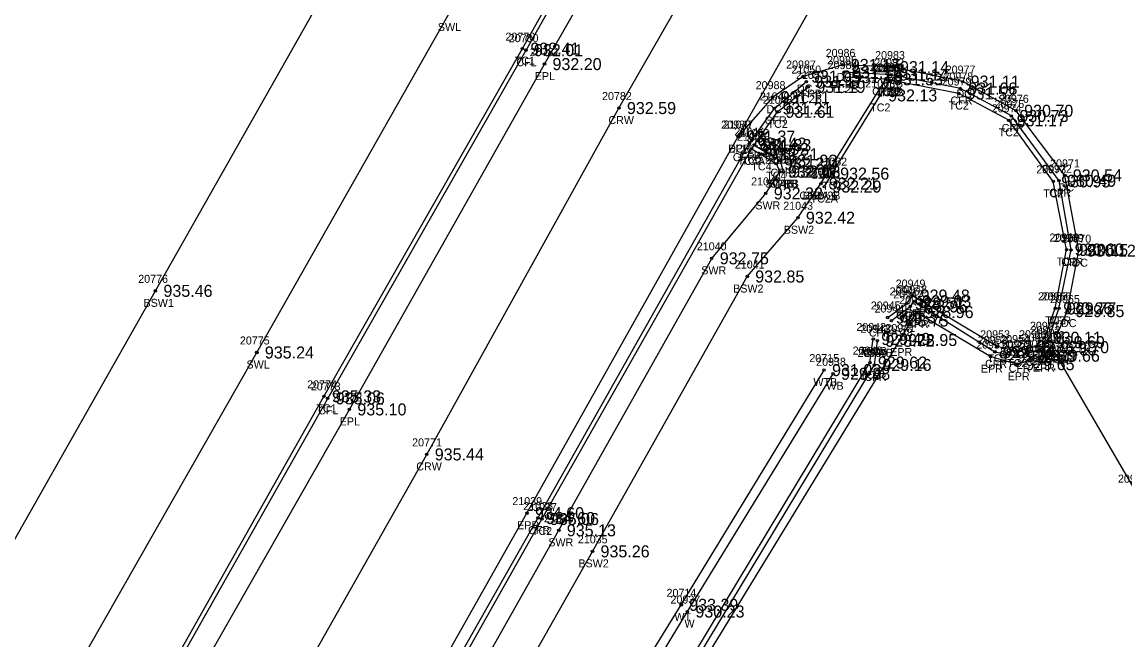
# Model space of a CAD drawing. Extents: x 1576181 to 1577685, y 1099396 to 1101490.
# Drawn here: x 1576648.9 to 1576786.7, y 1100049.3 to 1100126.4 of the extents above; entities that cross this region are included whole.
import ezdxf

# ---------------------------------------------------------------- set-up
doc = ezdxf.new("R2010")
doc.units = 0
for name, color, linetype in [('RD_DTM_BkLn1', 7, 'Continuous'), ('RD_DTM_BkLn2', 7, 'Continuous'), ('RD_EX_BldgApp', 7, 'Continuous'), ('RD_EX_Conc', 7, 'Continuous'), ('RD_EX_Conc_txCode', 7, 'Continuous'), ('RD_EX_Misc_txCode', 7, 'Continuous'), ('RD_EX_Road', 7, 'Continuous'), ('RD_EX_Road_txCode', 7, 'Continuous'), ('RD_EX_TX_Conc_ELEV', 7, 'Continuous'), ('RD_EX_TX_Misc_ELEV', 7, 'Continuous'), ('RD_EX_TX_Road_ELEV', 7, 'Continuous'), ('RD_HC_Survey_ELEV', 7, 'Continuous'), ('RD_HC_Survey_txCode', 7, 'Continuous'), ('RD_SMD_Locator', 7, 'Continuous')]:
    doc.layers.add(name, color=color, linetype=linetype)

msp = doc.modelspace()

# ---------------------------------------------------------------- linework, layer by layer
at = {"layer": 'RD_DTM_BkLn1'}
msp.add_lwpolyline([(1576435.96, 1099635.47), (1576469.98, 1099685.91), (1576496.51, 1099728.46), (1576522.67, 1099770.85), (1576549.06, 1099813.4), (1576563.36, 1099837.2), (1576575.09, 1099855.95), (1576600.75, 1099898.96), (1576625.57, 1099942.14), (1576652.37, 1099988.91), (1576675.03, 1100029.12), (1576699.51, 1100072.44), (1576723.52, 1100115.7), (1576748.08, 1100158.53), (1576774.13, 1100203.85), (1576797.97, 1100246.52), (1576822.46, 1100289.82), (1576846.93, 1100333.35), (1576871.37, 1100376.46), (1576888.27, 1100406.22)], dxfattribs=at)
at = {"layer": 'RD_DTM_BkLn2'}
for points in [[(1576569.71, 1099889.13), (1576574.56, 1099891.34), (1576579.27, 1099894.47), (1576584.19, 1099899.55), (1576592.25, 1099913.59), (1576612.84, 1099949.87), (1576637.54, 1099993.05), (1576637.54, 1099993.05), (1576662.19, 1100036.34), (1576686.67, 1100079.69), (1576711.46, 1100123.12), (1576735.92, 1100166.59), (1576760.76, 1100210.19), (1576785.21, 1100253.55), (1576809.13, 1100296.43), (1576833.85, 1100340.61), (1576852.06, 1100373.52), (1576858.66, 1100385.37)], [(1576749.19, 1100105.9), (1576750.16, 1100107.51), (1576756.16, 1100117.28), (1576757.41, 1100119.17)], [(1576757.11, 1100089.54), (1576759.48, 1100091.3), (1576760.22, 1100092.28), (1576770.78, 1100085.94), (1576773.28, 1100085.35), (1576775.63, 1100085.95), (1576776.72, 1100087.01), (1576778.03, 1100090.69), (1576779.46, 1100098.03), (1576777.79, 1100106.54), (1576772.22, 1100114.17), (1576765.97, 1100117.52), (1576757.41, 1100119.17), (1576756.86, 1100119.29), (1576751.73, 1100119.57)], [(1576665.05, 1099978.47), (1576689.17, 1100020.51), (1576713.89, 1100064.37), (1576740.09, 1100110.61), (1576743.33, 1100115.23), (1576747.19, 1100118.34)], [(1576740.09, 1100110.61), (1576741.31, 1100109.92), (1576743.17, 1100108.76), (1576743.62, 1100107.75)], [(1576691.33, 1099981.62), (1576693.77, 1099982.83), (1576694.95, 1099984.59), (1576706.06, 1099977.71), (1576709.96, 1099976.95), (1576712.68, 1099979.05), (1576716.84, 1099986.32), (1576717.28, 1099989.03), (1576715.05, 1099991.93), (1576703.59, 1099998.96), (1576727.24, 1100038.12), (1576754.88, 1100083.91), (1576755.29, 1100086.86)], [(1576682.86, 1099868.56), (1576662.28, 1099880.96), (1576644.68, 1099891.53), (1576640.03, 1099896.91), (1576640.01, 1099902.65), (1576645.38, 1099914.36), (1576654.84, 1099929.02), (1576680.05, 1099970.19), (1576705.64, 1100012.05), (1576731.3, 1100053.65), (1576749.15, 1100082.97)]]:
    msp.add_lwpolyline(points, dxfattribs=at)
at = {"layer": 'RD_EX_BldgApp'}
msp.add_lwpolyline([(1576672.29, 1099877.61), (1576646.3, 1099893.42), (1576642.27, 1099901.79), (1576647.56, 1099912.99), (1576656.83, 1099928.62), (1576681.63, 1099969.33), (1576707.3, 1100011.85), (1576732.08, 1100052.81), (1576750.28, 1100082.51)], dxfattribs=at)
at = {"layer": 'RD_EX_Conc'}
msp.add_line((1576748.75, 1100106.27), (1576756.86, 1100119.29), dxfattribs=at)
for points in [[(1576537.53, 1099904.47), (1576543.86, 1099909.52), (1576562.16, 1099910.99), (1576591.51, 1099962.44), (1576615.66, 1100005.02), (1576615.66, 1100005.02), (1576639.95, 1100047.65), (1576665.61, 1100092.87), (1576689.57, 1100135.17), (1576714.68, 1100179.66), (1576738.99, 1100222.53), (1576763.6, 1100265.87), (1576774.84, 1100284.48), (1576788.69, 1100308.17), (1576806.14, 1100353.34), (1576815.02, 1100384.28), (1576820.35, 1100399.92), (1576825.22, 1100406.93), (1576832.15, 1100418.17), (1576835.04, 1100423.11), (1576847.13, 1100416.35), (1576868.44, 1100408.23), (1576872.09, 1100412.69)], [(1576592.25, 1099913.59), (1576580.2, 1099912.49), (1576604.17, 1099954.86), (1576628.85, 1099997.89), (1576628.85, 1099997.89), (1576652.81, 1100040.47), (1576678.28, 1100085.17), (1576702.19, 1100127.32), (1576727.43, 1100172.04), (1576752.1, 1100215.39), (1576776.49, 1100258.76), (1576788, 1100277.34), (1576801.96, 1100301.42), (1576820.18, 1100348.3), (1576829.19, 1100379.59), (1576833.87, 1100393.41), (1576838.32, 1100402.43), (1576861.82, 1100391.11)], [(1576569.87, 1099888.69), (1576574.84, 1099890.86), (1576574.84, 1099890.86), (1576579.65, 1099894.15), (1576584.72, 1099899.29), (1576592.68, 1099913.3), (1576613.45, 1099949.72), (1576638.02, 1099992.78), (1576638.02, 1099992.78), (1576662.6, 1100036.05), (1576687.14, 1100079.44), (1576711.91, 1100122.93), (1576736.42, 1100166.35), (1576761.24, 1100209.96), (1576785.67, 1100253.17), (1576809.57, 1100296.25), (1576834.31, 1100340.56), (1576852.46, 1100373.22), (1576852.46, 1100373.22), (1576859.24, 1100385.1)], [(1576788.06, 1100067.91), (1576777.62, 1100085.83), (1576779.54, 1100090.34), (1576780.97, 1100097.89), (1576779.23, 1100107.29), (1576773.15, 1100115.36), (1576766.47, 1100119.01), (1576757.64, 1100120.82), (1576751.5, 1100121.09), (1576746.53, 1100119.64), (1576742.73, 1100117.06), (1576738.42, 1100112.14)], [(1576757.57, 1100089.16), (1576759.92, 1100090.92), (1576760.41, 1100091.57), (1576770.49, 1100085.25), (1576773.43, 1100084.71), (1576776.08, 1100085.54), (1576777.11, 1100086.46), (1576778.5, 1100090.67), (1576780.01, 1100097.98), (1576778.51, 1100106.62), (1576772.56, 1100114.71), (1576766.18, 1100118.14), (1576757.54, 1100119.87), (1576751.65, 1100120.18)], [(1576664.48, 1099978.73), (1576688.59, 1100020.79), (1576713.4, 1100064.49), (1576739.81, 1100111.26), (1576742.95, 1100115.66), (1576746.94, 1100119.01)], [(1576740.42, 1100111.07), (1576743.68, 1100109.13), (1576744.06, 1100107.76)], [(1576604.88, 1099870.26), (1576606.18, 1099869.97), (1576617.18, 1099889.59), (1576642.12, 1099933.62), (1576667.46, 1099977.42), (1576667.46, 1099977.42), (1576691.07, 1100018.79), (1576716.01, 1100062.96), (1576735.12, 1100096.93), (1576741.87, 1100105.04), (1576743.62, 1100107.75)], [(1576611.55, 1099868.43), (1576613.25, 1099872.41), (1576617.21, 1099879.29), (1576621.44, 1099887.05), (1576646.34, 1099930.82), (1576671.48, 1099974.6), (1576671.48, 1099974.6), (1576695.54, 1100016.68), (1576720.22, 1100060.33), (1576739.55, 1100094.66), (1576745.88, 1100102), (1576748.75, 1100106.27)], [(1576691.74, 1099981.25), (1576694.2, 1099982.62), (1576695.12, 1099983.85), (1576705.73, 1099977.15), (1576710.01, 1099976.47), (1576713.24, 1099978.71), (1576717.29, 1099985.96), (1576717.77, 1099989.3), (1576715.19, 1099992.27), (1576704.3, 1099999.11), (1576727.81, 1100037.82), (1576755.44, 1100083.61), (1576755.82, 1100086.63)]]:
    msp.add_lwpolyline(points, dxfattribs=at)
at = {"layer": 'RD_EX_Road'}
for points in [[(1576574.84, 1099890.86), (1576581.17, 1099887.16), (1576595.39, 1099911.97), (1576615.87, 1099948.17), (1576640.56, 1099991.4), (1576640.56, 1099991.4), (1576664.88, 1100034.19), (1576689.84, 1100078.06), (1576714.22, 1100121.19), (1576739.08, 1100164.66), (1576764.15, 1100209.11), (1576788.31, 1100251.8), (1576812.15, 1100294.46), (1576837.06, 1100339.37), (1576855.38, 1100371.53), (1576853.98, 1100372.48), (1576862.98, 1100388.86), (1576865.16, 1100391.95), (1576873.15, 1100402.8), (1576877.45, 1100410.32)], [(1576663.31, 1099979.53), (1576687.43, 1100021.53), (1576712.03, 1100065.1), (1576738.42, 1100112.14), (1576760.61, 1100151.41), (1576785.78, 1100195.96), (1576800.59, 1100221.87), (1576817.54, 1100252.08), (1576858.25, 1100324.63), (1576880.45, 1100364.01), (1576883.5, 1100369.45), (1576896.98, 1100397.71)], [(1576683.42, 1099888.98), (1576666.06, 1099899.54), (1576667.21, 1099902.21), (1576666.94, 1099905.87), (1576664.42, 1099908.53), (1576653.81, 1099914.11), (1576693.12, 1099978.42), (1576695.37, 1099982.47), (1576705.19, 1099976.43), (1576710.33, 1099975.62), (1576713.96, 1099978.17), (1576718.08, 1099985.44), (1576718.51, 1099989.55), (1576715.55, 1099993.27), (1576705.56, 1099999.56), (1576728.51, 1100037.37), (1576758.65, 1100086.73), (1576760.7, 1100090.22), (1576769.98, 1100084.65), (1576773.31, 1100083.71), (1576776.47, 1100084.77), (1576777.62, 1100085.83)]]:
    msp.add_lwpolyline(points, dxfattribs=at)
at = {"layer": 'RD_SMD_Locator'}
for centre in [(1576711.46, 1100123.12), (1576711.91, 1100122.93), (1576714.22, 1100121.19), (1576751.5, 1100121.09), (1576751.65, 1100120.18), (1576757.54, 1100119.87), (1576757.64, 1100120.82), (1576746.53, 1100119.64), (1576746.94, 1100119.01), (1576747.19, 1100118.34), (1576751.73, 1100119.57), (1576756.86, 1100119.29), (1576756.86, 1100119.29), (1576757.41, 1100119.17), (1576757.41, 1100119.17), (1576766.47, 1100119.01), (1576742.73, 1100117.06), (1576756.16, 1100117.28), (1576765.97, 1100117.52), (1576766.18, 1100118.14), (1576723.52, 1100115.7), (1576742.95, 1100115.66), (1576743.33, 1100115.23), (1576772.56, 1100114.71), (1576773.15, 1100115.36), (1576772.22, 1100114.17), (1576738.42, 1100112.14), (1576738.42, 1100112.14), (1576739.81, 1100111.26), (1576740.09, 1100110.61), (1576740.09, 1100110.61), (1576740.42, 1100111.07), (1576741.31, 1100109.92), (1576743.17, 1100108.76), (1576743.68, 1100109.13), (1576743.62, 1100107.75), (1576743.62, 1100107.75), (1576744.06, 1100107.76), (1576750.16, 1100107.51), (1576748.75, 1100106.27), (1576748.75, 1100106.27), (1576777.79, 1100106.54), (1576778.51, 1100106.62), (1576779.23, 1100107.29), (1576741.87, 1100105.04), (1576749.19, 1100105.9), (1576745.88, 1100102), (1576779.46, 1100098.03), (1576780.01, 1100097.98), (1576780.97, 1100097.89), (1576735.12, 1100096.93), (1576739.55, 1100094.66), (1576665.61, 1100092.87), (1576760.22, 1100092.28), (1576759.48, 1100091.3), (1576759.92, 1100090.92), (1576760.41, 1100091.57), (1576757.11, 1100089.54), (1576760.7, 1100090.22), (1576778.03, 1100090.69), (1576778.5, 1100090.67), (1576779.54, 1100090.34), (1576757.57, 1100089.16), (1576755.29, 1100086.86), (1576758.65, 1100086.73), (1576776.72, 1100087.01), (1576755.82, 1100086.63), (1576770.78, 1100085.94), (1576773.28, 1100085.35), (1576775.63, 1100085.95), (1576776.08, 1100085.54), (1576777.11, 1100086.46), (1576777.62, 1100085.83), (1576777.62, 1100085.83), (1576678.28, 1100085.17), (1576754.88, 1100083.91), (1576769.98, 1100084.65), (1576770.49, 1100085.25), (1576773.43, 1100084.71), (1576776.47, 1100084.77), (1576749.15, 1100082.97), (1576750.28, 1100082.51), (1576755.44, 1100083.61), (1576773.31, 1100083.71), (1576686.67, 1100079.69), (1576687.14, 1100079.44), (1576689.84, 1100078.06), (1576699.51, 1100072.44), (1576712.03, 1100065.1), (1576713.4, 1100064.49), (1576713.89, 1100064.37), (1576716.01, 1100062.96), (1576720.22, 1100060.33), (1576731.3, 1100053.65), (1576732.08, 1100052.81)]:
    msp.add_circle(centre, 0.15, dxfattribs=at)

# ---------------------------------------------------------------- texts
at = {"layer": 'RD_EX_Conc_txCode'}
for s, p in [('SWL', (1576700.9, 1100125.32)), ('20779', (1576709.34, 1100124.12)), ('20780', (1576709.75, 1100123.93)), ('20986', (1576749.35, 1100122.09)), ('20983', (1576755.53, 1100121.82)), ('TC1', (1576710.5, 1100121.12)), ('CFL', (1576710.7, 1100120.93)), ('20987', (1576744.41, 1100120.64)), ('20985', (1576749.53, 1100121.18)), ('20984', (1576749.61, 1100120.57)), ('21065', (1576755, 1100120.29)), ('20981', (1576755.03, 1100120.29)), ('20982', (1576755.42, 1100120.87)), ('21050', (1576745.07, 1100120.01)), ('21051', (1576745.64, 1100119.34)), ('DC', (1576750.72, 1100119.09)), ('20980', (1576755.25, 1100120.17)), ('21064', (1576755.55, 1100120.17)), ('20978', (1576764.06, 1100119.14)), ('20977', (1576764.35, 1100120.01)), ('20988', (1576740.61, 1100118.06)), ('DC', (1576745.75, 1100117.64)), ('CFRB', (1576749.95, 1100118.18)), ('TC2B', (1576750.01, 1100117.57)), ('21063', (1576754.3, 1100118.28)), ('CFR', (1576756.31, 1100117.87)), ('DC', (1576756.86, 1100118.82)), ('20979', (1576763.85, 1100118.52)), ('21049', (1576741.12, 1100116.66)), ('21048', (1576741.5, 1100116.23)), ('CFRB', (1576745.24, 1100117.01)), ('TC2B', (1576745.48, 1100116.34)), ('CFRB', (1576755.16, 1100117.29)), ('TC2', (1576755.62, 1100117.29)), ('TC2B', (1576755.69, 1100117.17)), ('TC2', (1576756.16, 1100117.17)), ('CFR', (1576764.95, 1100116.14)), ('DC', (1576765.69, 1100117.01)), ('20976', (1576771.01, 1100116.36)), ('DC', (1576741.95, 1100115.06)), ('TC2', (1576754.91, 1100115.28)), ('TC2', (1576764.72, 1100115.52)), ('20974', (1576770.1, 1100115.17)), ('20975', (1576770.45, 1100115.71)), ('CFR', (1576741.73, 1100113.66)), ('DC', (1576772.37, 1100113.36)), ('20989', (1576736.3, 1100113.14)), ('21046', (1576737.95, 1100112.26)), ('21052', (1576738.59, 1100112.07)), ('TC2', (1576742.09, 1100113.23)), ('TC2', (1576770.97, 1100112.17)), ('CFR', (1576771.34, 1100112.71)), ('21044', (1576738.26, 1100111.61)), ('21045', (1576738.26, 1100111.61)), ('21053', (1576739.47, 1100110.92)), ('DCB', (1576737.16, 1100110.14)), ('CFR', (1576738.58, 1100109.26)), ('21054', (1576741.33, 1100109.76)), ('21055', (1576741.85, 1100110.13)), ('CFRA 6', (1576737.75, 1100109.07)), ('TC4A', (1576738.36, 1100108.61)), ('TC2', (1576738.85, 1100108.61)), ('TC4', (1576740.07, 1100107.92)), ('21057', (1576741.79, 1100108.75)), ('21058', (1576741.79, 1100108.75)), ('21056', (1576742.2, 1100108.76)), ('21062', (1576748.31, 1100108.51)), ('20971', (1576777.39, 1100108.29)), ('TC4', (1576741.92, 1100106.76)), ('CFR', (1576742.45, 1100107.13)), ('21060', (1576746.85, 1100107.27)), ('21059', (1576746.91, 1100107.27)), ('21061', (1576747.61, 1100106.9)), ('20973', (1576775.67, 1100107.54)), ('20972', (1576776.39, 1100107.62)), ('21042', (1576740.04, 1100106.04)), ('SWRB', (1576741.83, 1100105.75)), ('TC4B', (1576741.9, 1100105.75)), ('CFRB', (1576742.36, 1100105.76)), ('TC2', (1576748.92, 1100105.51)), ('DC', (1576778.45, 1100105.29)), ('CFRA 6', (1576746.07, 1100104.27)), ('BSW2B', (1576746.51, 1100104.27)), ('TC2A', (1576747.46, 1100103.9)), ('TC2', (1576776.55, 1100104.54)), ('CFR', (1576777.28, 1100104.62)), ('SWR', (1576740.56, 1100103.04)), ('21043', (1576744.05, 1100103)), ('BSW2', (1576744.12, 1100100)), ('20968', (1576777.32, 1100099.03)), ('20969', (1576777.87, 1100098.98)), ('20970', (1576778.81, 1100098.89)), ('21040', (1576733.25, 1100097.93)), ('21041', (1576738, 1100095.66)), ('TC2', (1576778.22, 1100096.03)), ('CFR', (1576778.79, 1100095.98)), ('DC', (1576780.19, 1100095.89)), ('SWR', (1576733.81, 1100094.93)), ('20776', (1576663.46, 1100093.87)), ('20949', (1576758.1, 1100093.28)), ('BSW2', (1576737.79, 1100092.66)), ('20946', (1576757.34, 1100092.3)), ('20947', (1576757.8, 1100091.92)), ('20948', (1576758.3, 1100092.57)), ('20967', (1576775.89, 1100091.69)), ('20966', (1576776.33, 1100091.67)), ('20965', (1576777.4, 1100091.34)), ('BSW1', (1576664.12, 1100090.87)), ('20945', (1576754.99, 1100090.54)), ('20944', (1576755.46, 1100090.16)), ('TC2', (1576758.97, 1100090.28)), ('TC2', (1576758.24, 1100089.3)), ('CFR', (1576758.69, 1100088.92)), ('CFR', (1576759.19, 1100089.57)), ('TC2', (1576776.78, 1100088.69)), ('CFR', (1576777.27, 1100088.67)), ('20942', (1576753.18, 1100087.86)), ('20943', (1576753.7, 1100087.63)), ('CFRA 18', (1576754.75, 1100087.16)), ('TC2A', (1576755.37, 1100087.54)), ('20961', (1576774.87, 1100088.01)), ('20962', (1576774.96, 1100087.46)), ('DC', (1576778.76, 1100088.34)), ('20775', (1576676.16, 1100086.17)), ('20952', (1576768.37, 1100086.25)), ('20953', (1576768.66, 1100086.94)), ('20954', (1576771.16, 1100086.35)), ('20959', (1576773.51, 1100086.95)), ('20958', (1576773.96, 1100086.54)), ('20963', (1576775.48, 1100086.83)), ('20940', (1576752.72, 1100084.91)), ('20939', (1576753.32, 1100084.61)), ('TC2B', (1576753.58, 1100084.86)), ('CFRB', (1576754.12, 1100084.63)), ('20955', (1576771.32, 1100085.71)), ('TC2', (1576775.48, 1100085.01)), ('CFR', (1576775.88, 1100084.46)), ('SWL', (1576676.99, 1100083.17)), ('CFR', (1576769.26, 1100083.25)), ('TC2', (1576769.54, 1100083.94)), ('TC2', (1576772.04, 1100083.35)), ('TC2', (1576774.39, 1100083.95)), ('CFR', (1576774.85, 1100083.54)), ('DC', (1576776.84, 1100083.83)), ('TC2', (1576753.64, 1100081.91)), ('CFR', (1576772.21, 1100082.71)), ('20774', (1576684.56, 1100080.69)), ('20773', (1576685.02, 1100080.44)), ('CFR', (1576754.21, 1100081.61)), ('TC1', (1576685.71, 1100077.69)), ('CFL', (1576685.94, 1100077.44)), ('20960', (1576785.87, 1100068.91)), ('21038', (1576711.57, 1100065.49)), ('21037', (1576712.06, 1100065.37)), ('21036', (1576714.15, 1100063.96)), ('CFR', (1576712.17, 1100062.49)), ('TC2', (1576712.65, 1100062.37)), ('21035', (1576718.39, 1100061.33)), ('SWR', (1576714.7, 1100060.96)), ('BSW2', (1576718.46, 1100058.33))]:
    msp.add_text(s, height=1, dxfattribs=at).set_placement(p)
at = {"layer": 'RD_EX_Misc_txCode'}
for s, p in [('20715', (1576747.31, 1100083.97)), ('20938', (1576748.16, 1100083.51)), ('WTB', (1576747.82, 1100080.97)), ('WB', (1576749.44, 1100080.51)), ('20714', (1576729.47, 1100054.65)), ('20937', (1576729.96, 1100053.81)), ('WT', (1576730.45, 1100051.65)), ('W', (1576731.71, 1100050.81))]:
    msp.add_text(s, height=1, dxfattribs=at).set_placement(p)
at = {"layer": 'RD_EX_Road_txCode'}
for s, p in [('20781', (1576712.38, 1100122.19)), ('EPL', (1576713.01, 1100119.19)), ('21047', (1576736.58, 1100113.14)), ('EPR', (1576737.19, 1100110.14)), ('20950', (1576758.54, 1100091.22)), ('20941', (1576756.81, 1100087.73)), ('EPR', (1576759.47, 1100088.22)), ('20964', (1576775.48, 1100086.83)), ('EPR', (1576757.42, 1100084.73)), ('20951', (1576768.15, 1100085.65)), ('20956', (1576771.17, 1100084.71)), ('20957', (1576774.35, 1100085.77)), ('EPRB', (1576775.92, 1100083.83)), ('EPR', (1576768.75, 1100082.65)), ('EPR', (1576772.09, 1100081.71)), ('EPR', (1576775.24, 1100082.77)), ('20772', (1576687.72, 1100079.06)), ('EPL', (1576688.64, 1100076.06)), ('21039', (1576710.2, 1100066.1)), ('EPR', (1576710.8, 1100063.1))]:
    msp.add_text(s, height=1, dxfattribs=at).set_placement(p)
at = {"layer": 'RD_EX_TX_Conc_ELEV'}
for s, p in [('932.41', (1576712.46, 1100122.37)), ('932.01', (1576712.91, 1100122.18)), ('931.17', (1576752.5, 1100120.34)), ('931.14', (1576758.64, 1100120.07)), ('931.05', (1576747.53, 1100118.89)), ('931.12', (1576752.65, 1100119.43)), ('931.18', (1576752.73, 1100118.82)), ('931.53', (1576757.86, 1100118.54)), ('931.53', (1576757.86, 1100118.54)), ('931.63', (1576758.41, 1100118.42)), ('931.55', (1576758.41, 1100118.42)), ('931.14', (1576758.54, 1100119.12)), ('931.17', (1576747.94, 1100118.26)), ('931.19', (1576748.19, 1100117.59)), ('931.08', (1576767.18, 1100117.39)), ('931.11', (1576767.47, 1100118.26)), ('931.11', (1576743.73, 1100116.31)), ('932.13', (1576757.16, 1100116.53)), ('931.52', (1576766.97, 1100116.77)), ('931.21', (1576743.95, 1100114.91)), ('931.61', (1576744.33, 1100114.48)), ('930.70', (1576774.15, 1100114.61)), ('931.17', (1576773.22, 1100113.42)), ('930.73', (1576773.56, 1100113.96)), ('931.37', (1576739.42, 1100111.39)), ('931.42', (1576740.81, 1100110.51)), ('931.83', (1576741.42, 1100110.32)), ('931.92', (1576741.09, 1100109.86)), ('931.92', (1576741.09, 1100109.86)), ('932.21', (1576742.31, 1100109.17)), ('932.21', (1576744.17, 1100108.01)), ('931.93', (1576744.68, 1100108.38)), ('932.12', (1576744.62, 1100107)), ('932.12', (1576744.62, 1100107)), ('932.13', (1576745.06, 1100107.01)), ('932.56', (1576751.16, 1100106.76)), ('930.54', (1576780.23, 1100106.54)), ('932.21', (1576749.75, 1100105.52)), ('932.21', (1576749.75, 1100105.52)), ('932.29', (1576750.19, 1100105.15)), ('930.95', (1576778.79, 1100105.79)), ('930.49', (1576779.51, 1100105.87)), ('932.32', (1576742.87, 1100104.29)), ('932.42', (1576746.88, 1100101.25)), ('930.60', (1576780.46, 1100097.28)), ('930.15', (1576781.01, 1100097.23)), ('930.12', (1576781.97, 1100097.14)), ('932.75', (1576736.12, 1100096.18)), ('932.85', (1576740.55, 1100093.91)), ('935.46', (1576666.61, 1100092.12)), ('929.48', (1576761.22, 1100091.53)), ('929.03', (1576761.41, 1100090.82)), ('929.51', (1576760.48, 1100090.55)), ('928.96', (1576760.92, 1100090.17)), ('930.26', (1576779.03, 1100089.94)), ('929.77', (1576779.5, 1100089.92)), ('929.85', (1576780.54, 1100089.59)), ('929.37', (1576758.11, 1100088.79)), ('928.75', (1576758.57, 1100088.41)), ('929.49', (1576756.29, 1100086.11)), ('928.72', (1576756.82, 1100085.88)), ('930.11', (1576777.72, 1100086.26)), ('929.69', (1576778.11, 1100085.71)), ('935.24', (1576679.28, 1100084.42)), ('929.59', (1576771.49, 1100084.5)), ('930.02', (1576771.78, 1100085.19)), ('930.04', (1576774.28, 1100084.6)), ('929.60', (1576774.43, 1100083.96)), ('930.12', (1576776.63, 1100085.2)), ('929.60', (1576777.08, 1100084.79)), ('929.70', (1576778.62, 1100085.08)), ('929.62', (1576755.88, 1100083.16)), ('929.16', (1576756.44, 1100082.86)), ('935.33', (1576687.67, 1100078.94)), ('935.06', (1576688.14, 1100078.69)), ('934.60', (1576714.4, 1100063.74)), ('935.06', (1576714.89, 1100063.62)), ('935.13', (1576717.01, 1100062.21)), ('935.26', (1576721.22, 1100059.58))]:
    msp.add_text(s, height=1.5, dxfattribs=at).set_placement(p)
at = {"layer": 'RD_EX_TX_Misc_ELEV'}
for s, p in [('931.03', (1576750.15, 1100082.22)), ('929.88', (1576751.28, 1100081.76)), ('933.39', (1576732.3, 1100052.9)), ('930.23', (1576733.08, 1100052.06))]:
    msp.add_text(s, height=1.5, dxfattribs=at).set_placement(p)
at = {"layer": 'RD_EX_TX_Road_ELEV'}
for s, p in [('932.20', (1576715.22, 1100120.44)), ('931.37', (1576739.42, 1100111.39)), ('928.96', (1576761.7, 1100089.47)), ('928.95', (1576759.65, 1100085.98)), ('929.57', (1576770.98, 1100083.9)), ('929.66', (1576777.47, 1100084.02)), ('929.70', (1576778.62, 1100085.08)), ('929.65', (1576774.31, 1100082.96)), ('935.10', (1576690.84, 1100077.31)), ('934.60', (1576713.03, 1100064.35))]:
    msp.add_text(s, height=1.5, dxfattribs=at).set_placement(p)
at = {"layer": 'RD_HC_Survey_ELEV'}
for s, p in [('932.59', (1576724.52, 1100114.95)), ('935.44', (1576700.51, 1100071.69))]:
    msp.add_text(s, height=1.5, dxfattribs=at).set_placement(p)
at = {"layer": 'RD_HC_Survey_txCode'}
for s, p in [('20782', (1576721.41, 1100116.7)), ('CRW', (1576722.21, 1100113.7)), ('20771', (1576697.68, 1100073.44)), ('CRW', (1576698.2, 1100070.44))]:
    msp.add_text(s, height=1, dxfattribs=at).set_placement(p)

doc.saveas('drawing.dxf')
